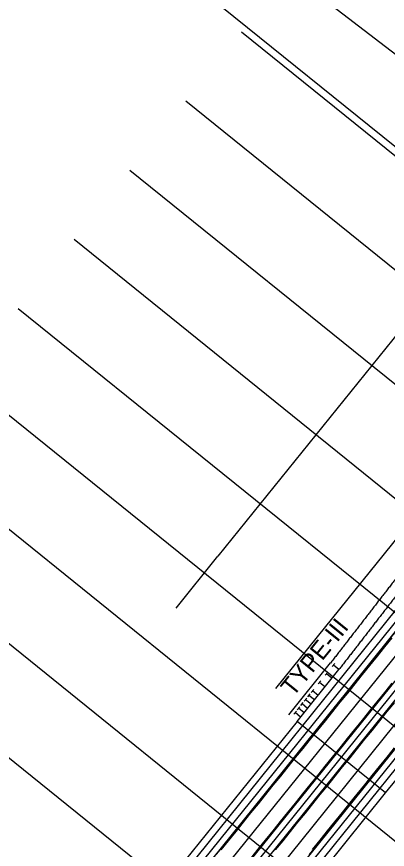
# Model space of a CAD drawing. Extents: x 2293233 to 2294507, y 892788 to 894229.
# Drawn here: x 2293888.9 to 2293993.2, y 893572.2 to 893806.4 of the extents above; entities that cross this region are included whole.
import ezdxf

# ---------------------------------------------------------------- set-up
doc = ezdxf.new("R2010")
doc.units = 0
for name, color, linetype in [('COGO Default Curve', 7, 'Continuous'), ('Prop EOT', 7, 'Continuous'), ('Prop Guardrail', 7, 'Continuous'), ('Prop Horizontal Alignment', 7, 'Continuous'), ('Prop Paved Shoulder', 7, 'Continuous'), ('Prop Roadway Bridge', 7, 'Continuous'), ('Prop Structure Anchor Unit CELL', 7, 'Continuous'), ('Scratch_Level_4', 7, 'Continuous'), ('Scratch_Level_5', 7, 'Continuous')]:
    doc.layers.add(name, color=color, linetype=linetype)

msp = doc.modelspace()

# ---------------------------------------------------------------- linework, layer by layer
at = {"layer": 'COGO Default Curve'}
for p, q in [((2293758.37, 893332.69), (2294065.5, 893713.27)), ((2293767.71, 893325.15), (2294074.84, 893705.73))]:
    msp.add_line(p, q, dxfattribs=at)
for points in [[(2294153.14, 893810.31), (2294150.2, 893805.46), (2294144.41, 893796.11), (2294138.51, 893786.83), (2294132.51, 893777.61), (2294126.4, 893768.47), (2294120.19, 893759.4), (2294113.87, 893750.39), (2294110.57, 893745.78), (2294107.25, 893741.2), (2294103.51, 893736.09), (2294099.53, 893730.74), (2294095.52, 893725.42), (2294091.47, 893720.12), (2294087.39, 893714.85), (2294083.28, 893709.6), (2294078.73, 893703.85), (2294073.94, 893697.86), (2293868.79, 893443.63)], [(2293934.91, 893558.24), (2293982.19, 893616.89), (2294012.67, 893654.83), (2294024.95, 893670.19), (2294035.75, 893683.75), (2294045.26, 893695.77), (2294053.92, 893706.78), (2294061.7, 893716.77), (2294068.83, 893726.01), (2294075.49, 893734.76), (2294081.7, 893743.02), (2294085.47, 893748.1), (2294089.22, 893753.21), (2294092.74, 893758.07), (2294096.24, 893762.94), (2294099.7, 893767.84), (2294102.95, 893772.49), (2294106.35, 893777.42), (2294109.73, 893782.38), (2294113.08, 893787.36), (2294116.39, 893792.36), (2294119.68, 893797.38), (2294123.12, 893802.7), (2294126.34, 893807.75)], [(2294137.26, 893807.39), (2294131.61, 893798.35), (2294125.85, 893789.36), (2294119.8, 893780.17), (2294113.84, 893771.33), (2294107.78, 893762.55), (2294101.61, 893753.84), (2294095.16, 893744.94), (2294091.39, 893739.84), (2294087.6, 893734.78), (2294083.76, 893729.73), (2294079.69, 893724.45), (2294075.59, 893719.2), (2294071.04, 893713.45), (2294059.17, 893698.61), (2294044.74, 893680.7), (2293954.06, 893568.41)], [(2293932.89, 893536.61), (2294046.75, 893677.72), (2294053.42, 893686.04), (2294059.44, 893693.61), (2294065.01, 893700.68), (2294070.34, 893707.51), (2294075.44, 893714.1), (2294080.29, 893720.46), (2294085.11, 893726.85), (2294089.69, 893733), (2294096.97, 893742.96), (2294103.95, 893752.72), (2294107.4, 893757.63), (2294110.82, 893762.56), (2294114.21, 893767.5), (2294117.58, 893772.47), (2294120.92, 893777.46), (2294124.04, 893782.19), (2294127.32, 893787.21), (2294130.39, 893791.98), (2294133.61, 893797.04), (2294136.62, 893801.84), (2294139.78, 893806.94)], [(2293995.33, 893633.22), (2293993.24, 893630.63), (2293991.15, 893628.03), (2293989.06, 893625.43), (2293986.97, 893622.83), (2293984.88, 893620.24), (2293982.79, 893617.64), (2293980.7, 893615.04), (2293978.61, 893612.45), (2293976.52, 893609.85), (2293974.43, 893607.26), (2293972.34, 893604.66), (2293970.25, 893602.06), (2293968.16, 893599.47), (2293966.07, 893596.87), (2293963.97, 893594.28), (2293961.88, 893591.68), (2293959.79, 893589.09), (2293957.7, 893586.49), (2293955.61, 893583.9), (2293953.51, 893581.3), (2293951.42, 893578.71), (2293949.33, 893576.11), (2293947.24, 893573.52), (2293945.14, 893570.92)], [(2293994.55, 893631.73), (2293992.46, 893629.13), (2293990.37, 893626.54), (2293988.27, 893623.94), (2293986.18, 893621.35), (2293984.09, 893618.76), (2293981.99, 893616.16), (2293979.9, 893613.57), (2293977.81, 893610.97), (2293975.71, 893608.38), (2293973.62, 893605.78), (2293971.52, 893603.19), (2293969.43, 893600.6), (2293967.34, 893598), (2293965.24, 893595.41), (2293963.15, 893592.81), (2293961.06, 893590.22), (2293958.96, 893587.62), (2293956.87, 893585.03), (2293954.78, 893582.44), (2293952.68, 893579.84), (2293950.59, 893577.25), (2293948.5, 893574.65), (2293946.4, 893572.06)], [(2293994.5, 893618.92), (2293992.41, 893616.33), (2293990.31, 893613.73), (2293988.22, 893611.14), (2293986.12, 893608.54), (2293984.03, 893605.95), (2293981.94, 893603.35), (2293979.84, 893600.76), (2293977.75, 893598.17), (2293975.66, 893595.57), (2293973.56, 893592.98), (2293971.47, 893590.38), (2293969.38, 893587.79), (2293967.28, 893585.19), (2293965.19, 893582.6), (2293963.1, 893580.01), (2293961, 893577.41), (2293958.91, 893574.82), (2293956.81, 893572.22), (2293954.72, 893569.63)], [(2293993.6, 893617.51), (2293991.5, 893614.91), (2293989.41, 893612.31), (2293987.32, 893609.71), (2293985.23, 893607.12), (2293983.14, 893604.52), (2293981.05, 893601.92), (2293978.96, 893599.33), (2293976.87, 893596.73), (2293974.78, 893594.14), (2293972.68, 893591.54), (2293970.59, 893588.94), (2293968.5, 893586.35), (2293966.41, 893583.75), (2293964.32, 893581.16), (2293962.22, 893578.56), (2293960.13, 893575.97), (2293958.04, 893573.37), (2293955.94, 893570.78)], [(2293961.81, 893572.05), (2293963.9, 893574.64), (2293966, 893577.23), (2293968.09, 893579.83), (2293970.19, 893582.42), (2293972.28, 893585.02), (2293974.37, 893587.61), (2293976.47, 893590.21), (2293978.56, 893592.8), (2293980.65, 893595.39), (2293982.75, 893597.99), (2293984.84, 893600.58), (2293986.93, 893603.18), (2293989.03, 893605.77), (2293991.12, 893608.37), (2293993.22, 893610.96), (2293995.31, 893613.55)], [(2293960.57, 893570.91), (2293962.67, 893573.51), (2293964.76, 893576.1), (2293966.85, 893578.69), (2293968.95, 893581.29), (2293971.04, 893583.88), (2293973.14, 893586.48), (2293975.23, 893589.07), (2293977.32, 893591.67), (2293979.42, 893594.26), (2293981.51, 893596.85), (2293983.6, 893599.45), (2293985.7, 893602.04), (2293987.79, 893604.64), (2293989.88, 893607.23), (2293991.98, 893609.83), (2293994.07, 893612.42)], [(2293971.38, 893570.76), (2293973.47, 893573.36), (2293975.56, 893575.95), (2293977.66, 893578.54), (2293979.75, 893581.14), (2293981.84, 893583.73), (2293983.94, 893586.33), (2293986.03, 893588.92), (2293988.12, 893591.52), (2293990.22, 893594.11), (2293992.31, 893596.7), (2293994.41, 893599.3)], [(2293972.22, 893572.21), (2293974.32, 893574.8), (2293976.41, 893577.4), (2293978.51, 893579.99), (2293980.6, 893582.59), (2293982.69, 893585.18), (2293984.79, 893587.78), (2293986.88, 893590.37), (2293988.97, 893592.96), (2293991.07, 893595.56), (2293993.16, 893598.15), (2293995.25, 893600.75)]]:
    msp.add_lwpolyline(points, dxfattribs=at)
at = {"layer": 'Prop EOT'}
for p, q in [((2293753.7, 893336.46), (2294060.83, 893717.04)), ((2293753.7, 893336.46), (2294060.83, 893717.04)), ((2293772.37, 893321.38), (2294079.51, 893701.97))]:
    msp.add_line(p, q, dxfattribs=at)
at = {"layer": 'Prop Guardrail'}
msp.add_spline([(2294010.25, 893662.32), (2294009.84, 893661.79), (2294009.42, 893661.25), (2294009.01, 893660.72), (2294008.6, 893660.19), (2294008.18, 893659.65), (2294007.77, 893659.12), (2294007.35, 893658.58), (2294006.94, 893658.05), (2294006.53, 893657.51), (2294006.11, 893656.98), (2294005.7, 893656.45), (2294005.29, 893655.91), (2294004.87, 893655.38), (2294004.46, 893654.84), (2294004.04, 893654.31), (2294003.63, 893653.77), (2294003.22, 893653.24), (2294002.8, 893652.71), (2294002.39, 893652.17), (2294001.97, 893651.64), (2294001.56, 893651.1), (2294001.15, 893650.57), (2294000.73, 893650.03), (2294000.32, 893649.5), (2293999.91, 893648.97), (2293999.49, 893648.43), (2293999.08, 893647.9), (2293998.66, 893647.36), (2293998.25, 893646.83), (2293997.84, 893646.29), (2293997.42, 893645.76), (2293997.01, 893645.23), (2293996.59, 893644.69), (2293996.18, 893644.16), (2293995.77, 893643.62), (2293995.35, 893643.09), (2293994.94, 893642.55), (2293994.53, 893642.02), (2293994.11, 893641.49), (2293993.7, 893640.95), (2293993.28, 893640.42), (2293992.87, 893639.88), (2293992.46, 893639.35), (2293992.04, 893638.81), (2293991.63, 893638.28), (2293991.22, 893637.75), (2293990.8, 893637.21), (2293990.39, 893636.68), (2293989.97, 893636.14), (2293989.56, 893635.61), (2293989.15, 893635.07), (2293988.73, 893634.54), (2293988.32, 893634.01), (2293987.9, 893633.47), (2293987.49, 893632.94), (2293987.08, 893632.4), (2293986.66, 893631.87), (2293986.25, 893631.33), (2293985.84, 893630.8), (2293985.42, 893630.27), (2293985.01, 893629.73), (2293984.59, 893629.2), (2293984.18, 893628.66), (2293983.77, 893628.13), (2293983.35, 893627.59), (2293982.94, 893627.06), (2293982.53, 893626.52), (2293982.11, 893625.99), (2293981.7, 893625.46), (2293981.28, 893624.92), (2293980.87, 893624.39), (2293980.46, 893623.85), (2293980.04, 893623.32), (2293979.63, 893622.78)], degree=3, dxfattribs=at)
at = {"layer": 'Prop Horizontal Alignment'}
for p, q in [((2294069, 893710.44), (2293856.16, 893882.21)), ((2293763.04, 893328.92), (2294070.17, 893709.5)), ((2293763.04, 893328.92), (2294070.17, 893709.5))]:
    msp.add_line(p, q, dxfattribs=at)
at = {"layer": 'Prop Paved Shoulder'}
for p, q in [((2293752.14, 893337.71), (2294059.27, 893718.29)), ((2293773.93, 893320.13), (2294081.06, 893700.71))]:
    msp.add_line(p, q, dxfattribs=at)
at = {"layer": 'Prop Roadway Bridge'}
for p, q in [((2293967.85, 893608.19), (2293839.83, 893449.55)), ((2293992.76, 893588.1), (2293967.85, 893608.19)), ((2293864.73, 893429.45), (2293992.76, 893588.1))]:
    msp.add_line(p, q, dxfattribs=at)
at = {"layer": 'Prop Structure Anchor Unit CELL'}
for p, q in [((2293977.71, 893623.6), (2293978.43, 893624.49)), ((2293967.85, 893608.19), (2293979.63, 893622.78)), ((2293979.63, 893622.78), (2293978.07, 893624.04)), ((2293975.75, 893621.16), (2293976.47, 893622.05)), ((2293977.67, 893620.35), (2293976.11, 893621.61)), ((2293973.79, 893618.73), (2293974.51, 893619.62)), ((2293975.7, 893617.92), (2293974.15, 893619.18)), ((2293970.84, 893615.08), (2293971.56, 893615.98)), ((2293972.76, 893614.27), (2293971.2, 893615.53)), ((2293971.82, 893616.3), (2293972.54, 893617.19)), ((2293973.74, 893615.49), (2293972.18, 893616.75)), ((2293968.88, 893612.65), (2293969.6, 893613.54)), ((2293970.8, 893611.84), (2293969.24, 893613.1)), ((2293969.86, 893613.87), (2293970.58, 893614.76)), ((2293971.78, 893613.06), (2293970.22, 893614.31)), ((2293966.92, 893610.22), (2293967.64, 893611.11)), ((2293968.83, 893609.41), (2293967.28, 893610.67)), ((2293967.9, 893611.44), (2293968.62, 893612.33)), ((2293969.82, 893610.63), (2293968.26, 893611.88)), ((2293992.76, 893588.1), (2294004.53, 893602.69))]:
    msp.add_line(p, q, dxfattribs=at)
at = {"layer": 'Scratch_Level_4'}
for p, q in [((2293965.44, 893818.95), (2294203.4, 893636.27)), ((2293952.21, 893802.18), (2294185.67, 893613.78)), ((2293708.32, 893261.12), (2294130.82, 893784.65)), ((2293936.51, 893782.73), (2294169.97, 893594.32)), ((2293920.81, 893763.27), (2294154.27, 893574.87)), ((2293905.11, 893743.82), (2294138.57, 893555.41)), ((2293889.41, 893724.36), (2294122.87, 893535.96)), ((2293873.71, 893704.91), (2294107.17, 893516.5)), ((2293858.01, 893685.45), (2294091.47, 893497.05)), ((2293842.31, 893666), (2294075.77, 893477.59)), ((2293826.61, 893646.54), (2294060.07, 893458.14))]:
    msp.add_line(p, q, dxfattribs=at)
at = {"layer": 'Scratch_Level_5'}
for p, q in [((2294086.88, 893829.74), (2293945.58, 893654.65)), ((2293973.61, 893632.03), (2294020.71, 893690.39)), ((2293933.8, 893640.06), (2293945.58, 893654.65)), ((2293961.83, 893617.44), (2293973.61, 893632.03)), ((2293965.52, 893610.08), (2293977.29, 893624.67))]:
    msp.add_line(p, q, dxfattribs=at)
msp.add_spline([(2294007.88, 893664.16), (2294007.47, 893663.63), (2294007.05, 893663.09), (2294006.64, 893662.56), (2294006.22, 893662.02), (2294005.81, 893661.49), (2294005.4, 893660.95), (2294004.98, 893660.42), (2294004.57, 893659.89), (2294004.15, 893659.35), (2294003.74, 893658.82), (2294003.33, 893658.28), (2294002.91, 893657.75), (2294002.5, 893657.21), (2294002.09, 893656.68), (2294001.67, 893656.15), (2294001.26, 893655.61), (2294000.84, 893655.08), (2294000.43, 893654.54), (2294000.02, 893654.01), (2293999.6, 893653.47), (2293999.19, 893652.94), (2293998.78, 893652.41), (2293998.36, 893651.87), (2293997.95, 893651.34), (2293997.53, 893650.8), (2293997.12, 893650.27), (2293996.71, 893649.73), (2293996.29, 893649.2), (2293995.88, 893648.67), (2293995.46, 893648.13), (2293995.05, 893647.6), (2293994.64, 893647.06), (2293994.22, 893646.53), (2293993.81, 893645.99), (2293993.4, 893645.46), (2293992.98, 893644.93), (2293992.57, 893644.39), (2293992.15, 893643.86), (2293991.74, 893643.32), (2293991.33, 893642.79), (2293990.91, 893642.25), (2293990.5, 893641.72), (2293990.08, 893641.19), (2293989.67, 893640.65), (2293989.26, 893640.12), (2293988.84, 893639.58), (2293988.43, 893639.05), (2293988.02, 893638.51), (2293987.6, 893637.98), (2293987.19, 893637.44), (2293986.77, 893636.91), (2293986.36, 893636.38), (2293985.95, 893635.84), (2293985.53, 893635.31), (2293985.12, 893634.77), (2293984.71, 893634.24), (2293984.29, 893633.7), (2293983.88, 893633.17), (2293983.46, 893632.64), (2293983.05, 893632.1), (2293982.64, 893631.57), (2293982.22, 893631.03), (2293981.81, 893630.5), (2293981.39, 893629.96), (2293980.98, 893629.43), (2293980.57, 893628.9), (2293980.15, 893628.36), (2293979.74, 893627.83), (2293979.33, 893627.29), (2293978.91, 893626.76), (2293978.5, 893626.22), (2293978.08, 893625.69), (2293977.67, 893625.16), (2293977.26, 893624.62)], degree=3, dxfattribs=at)

# ---------------------------------------------------------------- texts
at = {"layer": 'Prop Structure Anchor Unit CELL'}
msp.add_text('TYPE-III', height=5, rotation=51.0748, dxfattribs=at).set_placement((2293966.75, 893614.92))

doc.saveas('drawing.dxf')
